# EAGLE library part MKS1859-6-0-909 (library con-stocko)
Serie MKS 1850 Lötstifte In-line, Raster 2.5 mm, Stiftwannen, stehend, mit Rastlasche Source: http://www.stocko.de/de/index.php?seite=ka_rfk2_mks1850.html&rubrik=Katalog+-+RFK+2 rfk_1850.pdf
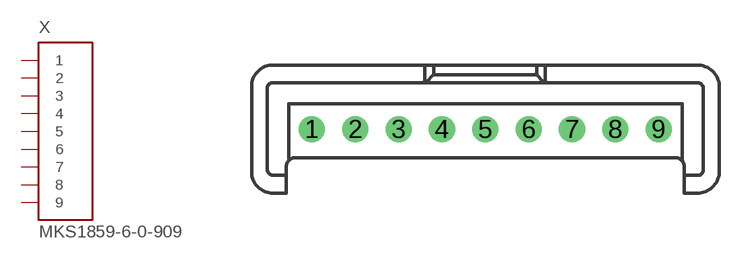
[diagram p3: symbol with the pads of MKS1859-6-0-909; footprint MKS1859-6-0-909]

Designator prefix X

## MKS1859-6-0-909 (OC_FARNELL: unknown; OC_NEWARK: unknown)  [MKS1859-6-0-909]
1  1  in
2  2  in
3  3  in
4  4  in
5  5  in
6  6  in
7  7  in
8  8  in
9  9  in

## Footprint MKS1859-6-0-909 (pad centres in mm)
Serie MKS 1850 Lötstifte In-line, Raster 2.5 mm, Stiftwannen, stehend, mit Rastlasche Source: http://www.stocko.de/de/index.php?seite=ka_rfk2_mks1850.html&rubrik=Katalog+-+RFK+2 rfk_1850.pdf
drill 1 pad 1.422 round: 1 -10,0; 2 -7.5,0; 3 -5,0; 4 -2.5,0; 5 0,0; 6 2.5,0; 7 5,0; 8 7.5,0; 9 10,0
